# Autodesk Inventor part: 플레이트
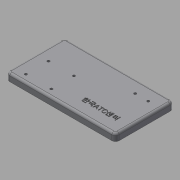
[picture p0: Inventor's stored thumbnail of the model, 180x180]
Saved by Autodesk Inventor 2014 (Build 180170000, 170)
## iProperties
Created: 2018-01
Part Number: 플레이트
Material: 일반
Document SubType Name: Modeling
Designer: mduedu
Density: 1 g/cm^3
Appearance: 기본값
Author: mduedu
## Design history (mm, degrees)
sketch "스케치1"
  geometry: L1 (75, 40)-(-75, 40); L2 (-75, 40)-(-75, -40); L3 (-75, -40)-(75, -40); L4 (75, -40)-(75, 40); L5 (75, 40)-(-75, -40); L6 (-75, 40)-(75, -40); 1 further point
  constraints: 12 end point, 2 midpoint, 2 parallel, 1 horizontal, 1 perpendicular
  dimensions: "d0" = 150 distance of L3.end L2.end; "d1" = 80 distance of L2.end L1.end
extrude "돌출1" new body sketch "스케치1" distance "d2" = 10; taper "d3" = 0 deg
fillet "모깎기1" dims "d4" = 5
fillet "모깎기2" dims "d5" = 3
sketch "스케치2"
  geometry: L1 (-70, 40)-(70, 40) reference; L2 (-75, -35)-(-75, 35) reference; 5 further points
  constraints: 2 horizontal alignment, 2 vertical alignment
  dimensions: "d6" = 10 distance from line of point (-58, 30) L1; "d7" = 35 distance of point (-23, 30) point (-58, 30); "d8" = 31 distance of point (-58, -1) point (-58, 30); "d9" = 17 distance from line of point (-58, 30) L2
sketch "스케치3"
  geometry: 4 further points
  constraints: 4 other
hole "구멍1" sketch "스케치3" at (-23, 30), (-58, -1), (-23, -1), (-58, 30) diameter "d10" = 3.4; stored, may be unused: countersink angle "d14" = 90 deg, drill point angle "d16" = 0 deg; dims "d11" = 6, "d12" = 6.5, "d13" = 3.4, "d15" = 8
sketch "스케치4"
  geometry: L1 (75, 35)-(75, -35) reference; L2 (70, -40)-(-70, -40) reference; 3 further points
  constraints: 1 horizontal alignment
  dimensions: "d17" = 17 distance from line of point (58, -22) L1; "d18" = 18 distance of point (40, -22) point (58, -22); "d19" = 18 distance from line of point (58, -22) L2
sketch "스케치5"
  geometry: 2 further points
  constraints: 2 other
hole "구멍2" sketch "스케치5" at (40, -22), (58, -22) diameter "d20" = 3.4; stored, may be unused: countersink angle "d24" = 90 deg, drill point angle "d26" = 0 deg; dims "d21" = 6, "d22" = 6.5, "d23" = 3.4, "d25" = 8
sketch "스케치6"
  geometry: L1 (75, -35)-(75, 35) reference; L2 (-70, -40)-(70, -40) reference; 2 further points
  constraints: 1 other
  dimensions: "d27" = 40 distance from line of point (35, -20) L1; "d28" = 20 distance from line of point (35, -20) L2
feature "엠보싱1" sketch "스케치6" dims "d0" = 150, "d29" = 0.5, "d30" = 0
node "솔리드1"
